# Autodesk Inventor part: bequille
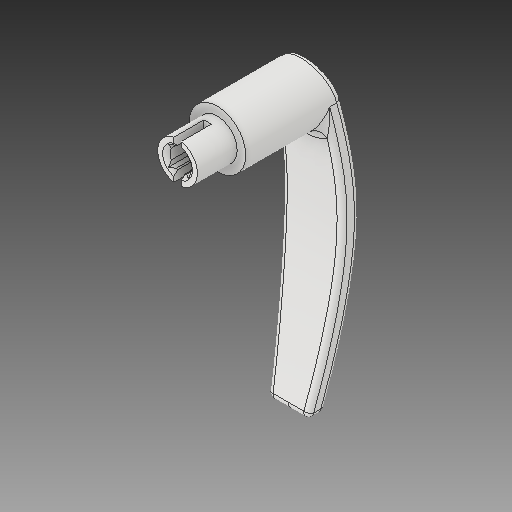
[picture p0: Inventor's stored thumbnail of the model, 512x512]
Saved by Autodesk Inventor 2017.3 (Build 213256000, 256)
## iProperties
Created: 2008-01
Part Number: bequille
Material: Générique
Document SubType Name: Modeling
Designer: ficho
Density: 1 g/cm^3
Appearance: Par défaut
Author: ficho
Sending System: SolidWorks 2009
Last Author: christophe
Last Saved: 2011-01-23
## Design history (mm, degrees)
feature "Congé38"
node "Solide1"
